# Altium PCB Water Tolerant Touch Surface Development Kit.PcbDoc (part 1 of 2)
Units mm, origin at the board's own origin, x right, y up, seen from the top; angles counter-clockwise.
Board outline 95 x 75 mm, 2 copper layers (Top Layer, Bottom Layer); 89 components, 87 nets, 311 pads, 203 vias.
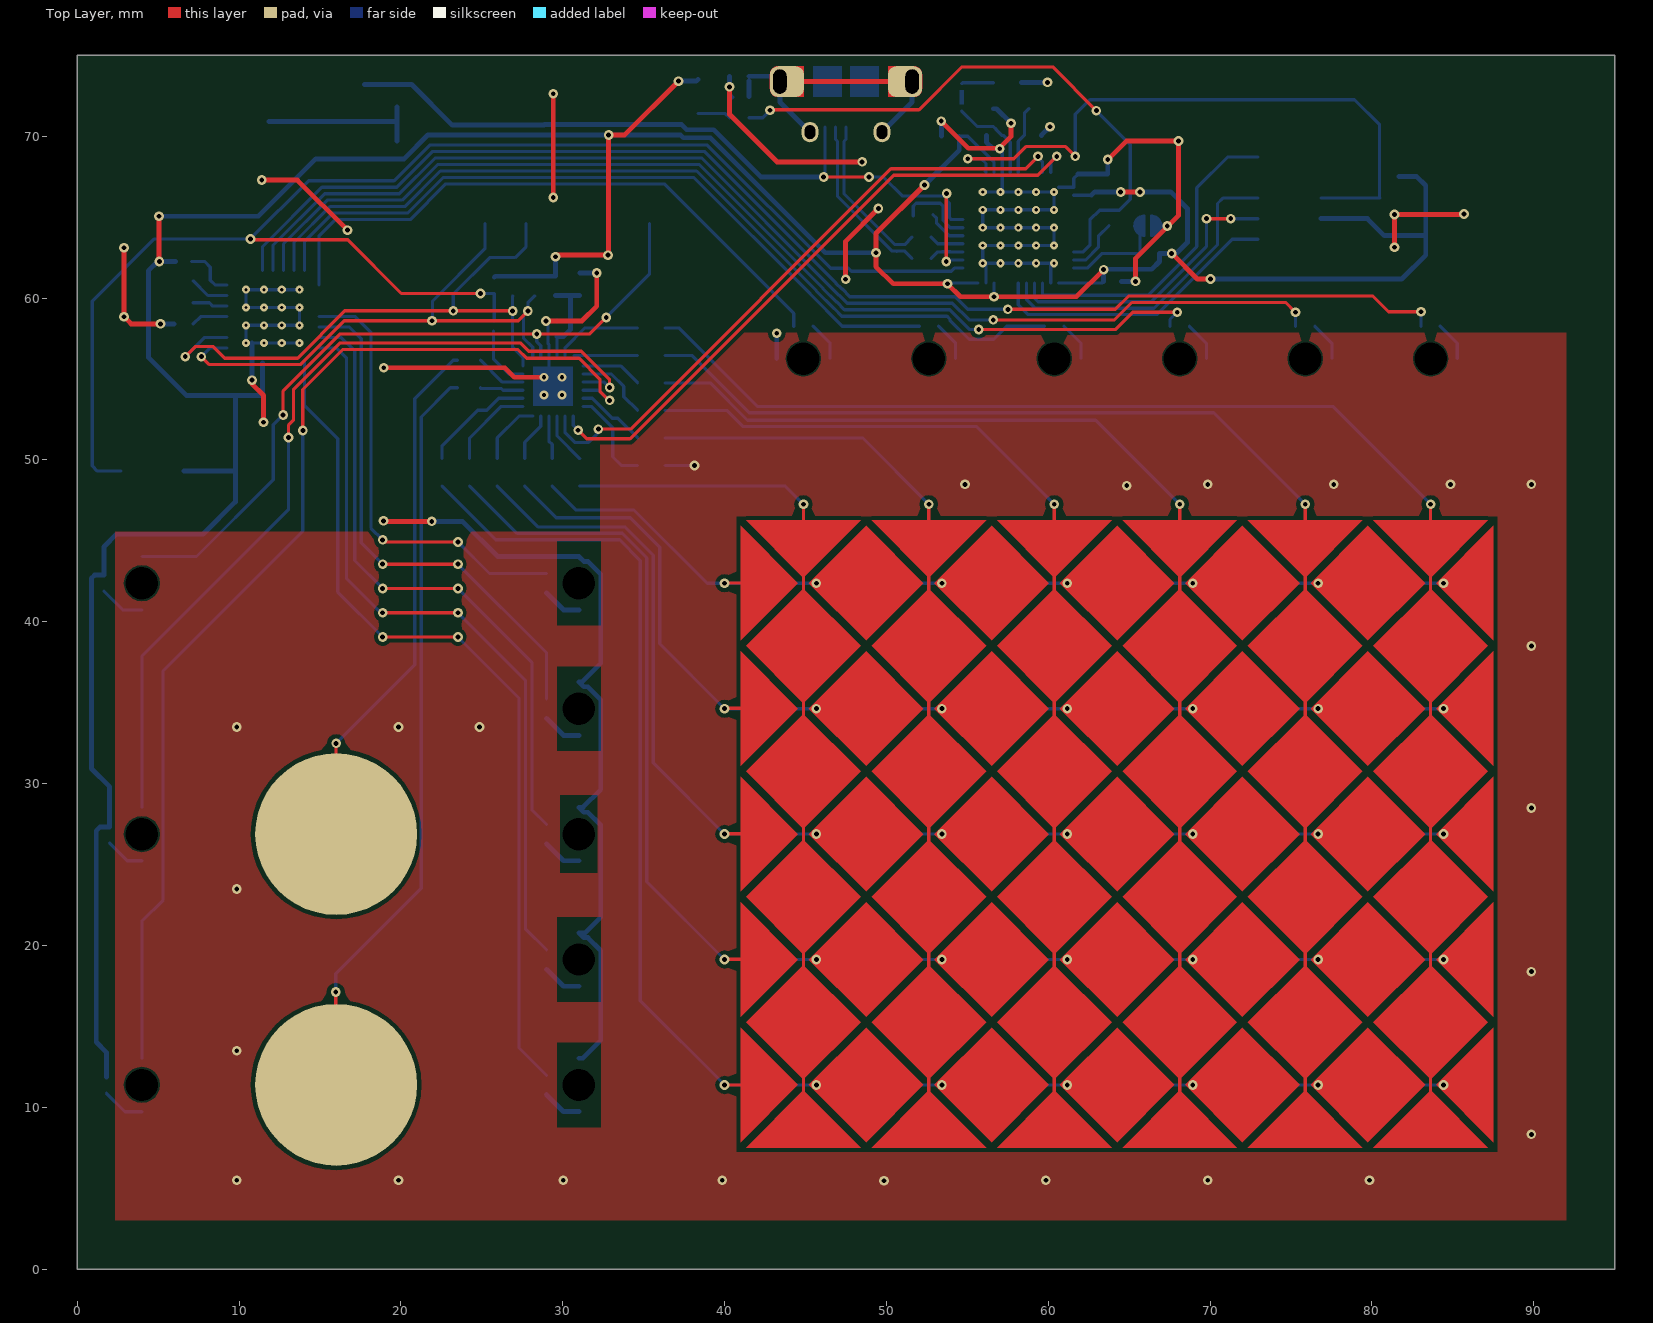
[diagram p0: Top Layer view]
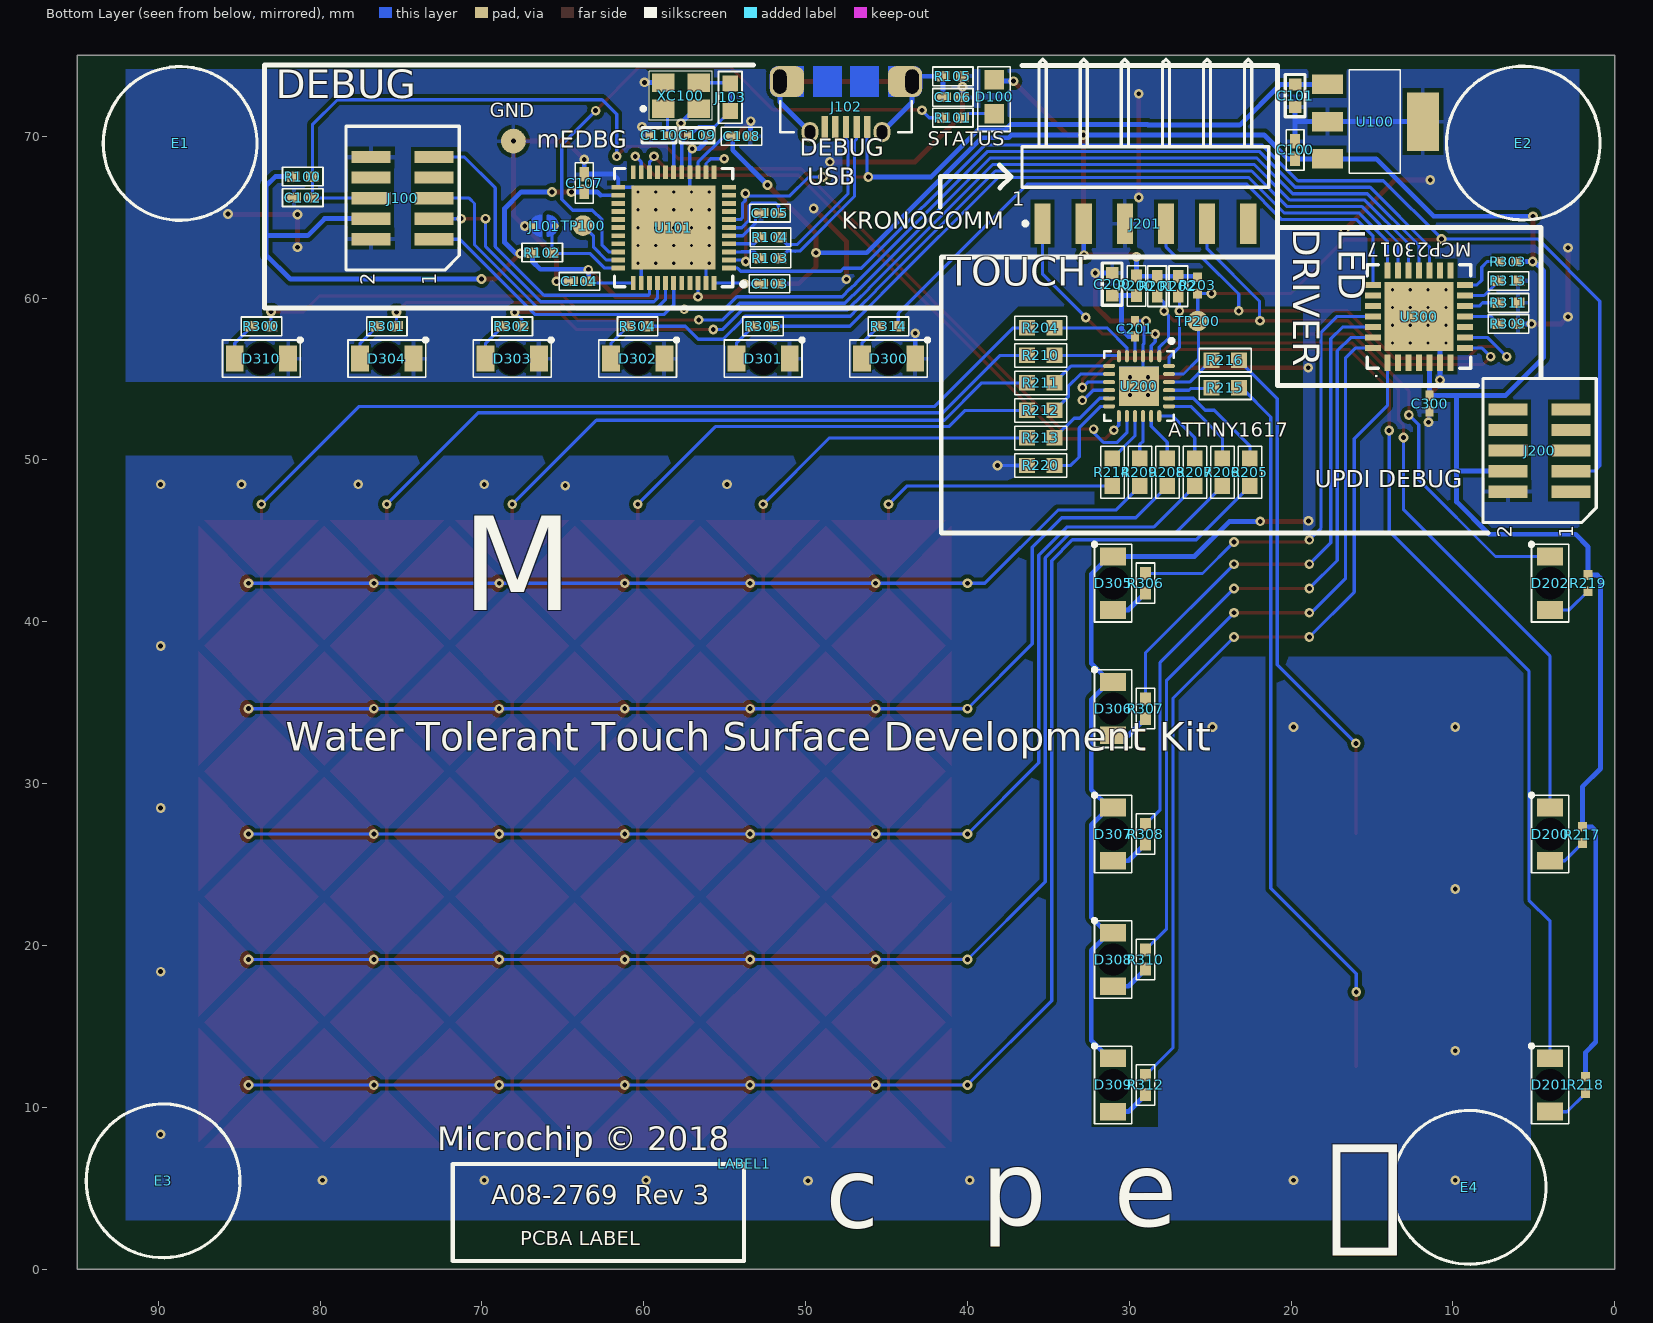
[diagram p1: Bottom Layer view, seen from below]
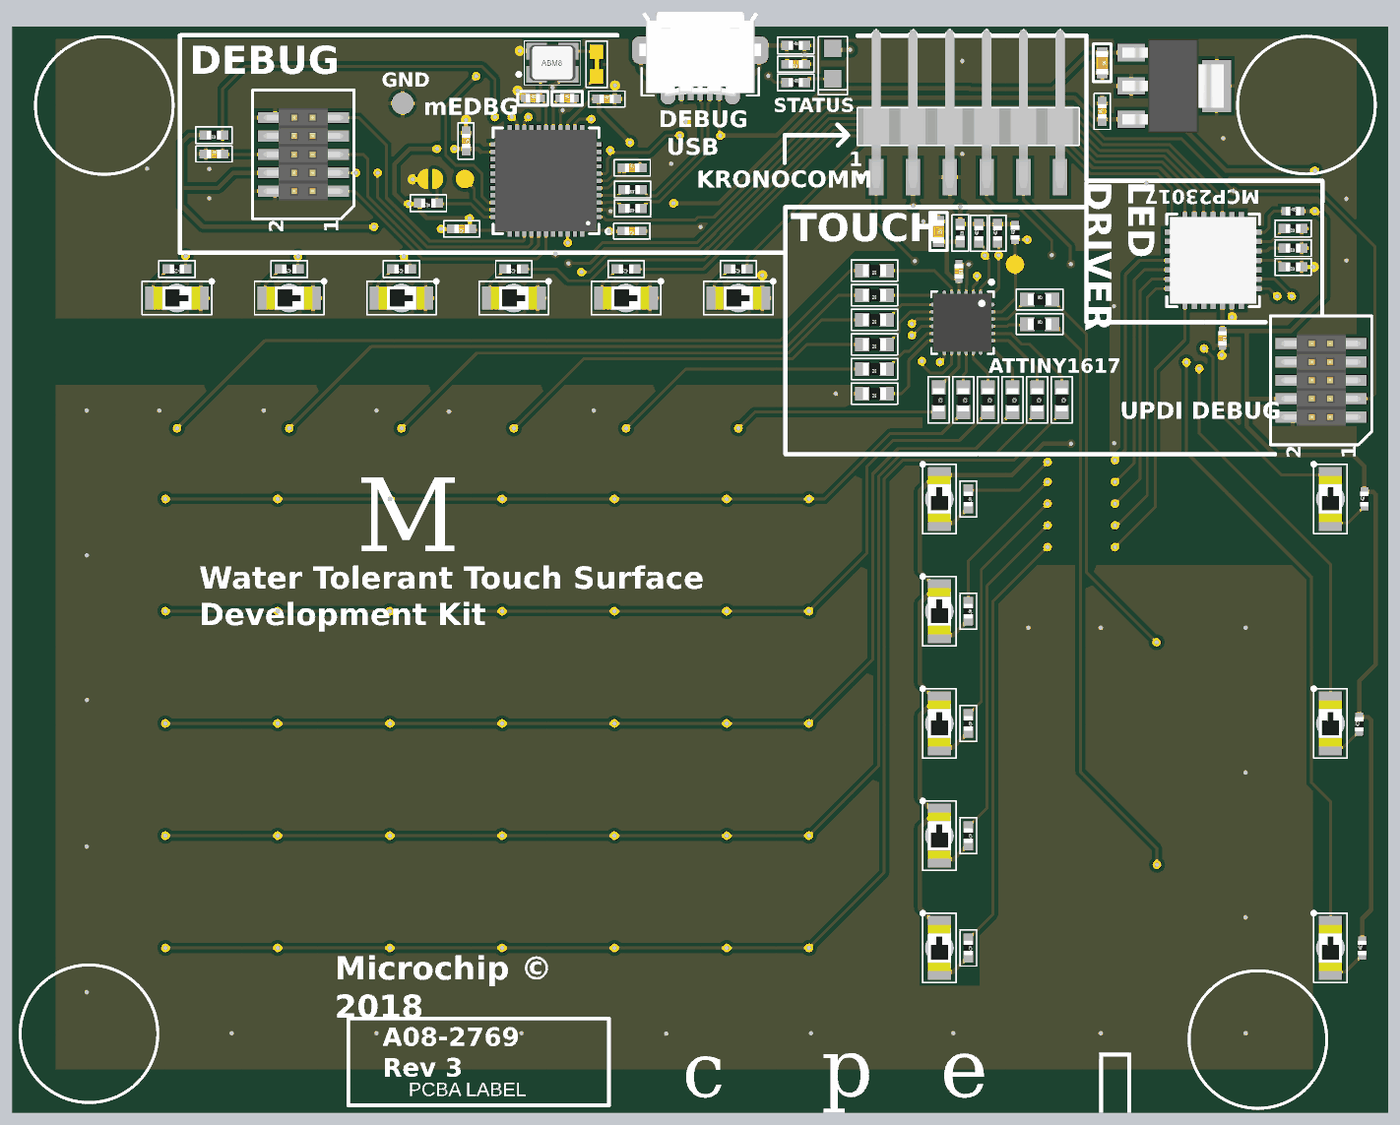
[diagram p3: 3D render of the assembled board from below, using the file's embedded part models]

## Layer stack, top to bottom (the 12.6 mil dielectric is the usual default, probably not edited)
Top Solder: solder mask 0.0102, Solder Resist, Dk 3.5
Top Layer: signal copper 0.0356
Dielectric 1: dielectric 0.32, FR-4, Dk 4.8
Bottom Layer: signal copper 0.0356
Bottom Solder: solder mask 0.0102, Solder Resist, Dk 3.5

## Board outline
0.007,0 0.007,75 95.007,75 95.007,0

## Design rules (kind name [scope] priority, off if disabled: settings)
AcuteAngle [All] p1: minimum=7.00000000000000E+0001 checktracksonly=FALSE
AssemblyTestPointUsage "Schematic Assembly Testpoint Usage_4" [InNet('NetJ103_1')] p1: valid=1
AssemblyTestPointUsage "Schematic Assembly Testpoint Usage_3" [InNet('XTAL1')] p2: valid=1
AssemblyTestPointUsage "Schematic Assembly Testpoint Usage_2" [InNet('XTAL2')] p3: valid=1
AssemblyTestPointUsage "Schematic Assembly Testpoint Usage_1" [InNet('D_P')] p4: valid=1
AssemblyTestPointUsage "Schematic Assembly Testpoint Usage" [InNet('D_N')] p5: valid=1
AssemblyTestPointUsage [All] p6: allowmultiple=TRUE
AssemblyTestpoint [(IsPad And OnMultiLayer)] p1: testpointundercomponent=TRUE minsize=0.55 maxsize=2 preferedsize=0.8 minholesize=0 maxholesize=1 preferedholesize=0.25 testpointgrid=0.025 usegrid=FALSE gridtolerance=0 allowsidebottom=TRUE minspacing=1.27 compbodyclearance=0.127
Clearance Clearance_AP4-00115 [All vs HasFootprint('AP4-00115')] p1: gap=0.1 ignorepadtopadclearanceinfootprint=FALSE except(0: Arc-Hole Track-Hole SMDPad-Hole THPad-Hole Via-Hole Fill-Hole Poly-Hole Region-Hole Text-Hole)
Clearance Clearance_KEEPOUT [IsKeepOut] p2: gap=0.4 ignorepadtopadclearanceinfootprint=FALSE except(0: Arc-Hole Track-Hole SMDPad-Hole THPad-Hole Via-Hole Fill-Hole Poly-Hole Region-Hole Text-Hole)
Clearance Clearance_POLY [InPolygon] p3: gap=0.25 ignorepadtopadclearanceinfootprint=FALSE except(0: Arc-Hole Track-Hole SMDPad-Hole THPad-Hole Via-Hole Fill-Hole Poly-Hole Region-Hole Text-Hole)
Clearance [All] p4: gap=0.2 ignorepadtopadclearanceinfootprint=FALSE except(0: Arc-Hole Track-Hole SMDPad-Hole THPad-Hole Via-Hole Fill-Hole Poly-Hole Region-Hole Text-Hole)
ComponentClearance [All] p1: gap=0.1 collisioncheckmode=3 verticalgap=0.1 showdistances=FALSE
DiffPairsRouting [All] p1: maxlimit=0.3 minlimit=0.2 mostfreqgap=0.2 toplayer_minwidth=0.18 toplayer_maxwidth=0.2 toplayer_prefwidth=0.2 bottomlayer_minwidth=0.18 bottomlayer_maxwidth=0.2 bottomlayer_prefwidth=0.2 maxuncoupledlength=20
FabricationTestPointUsage TestPointUsage [All] p1: valid=0 allowmultiple=TRUE
FabricationTestpoint Testpoint [(IsPad And OnMultiLayer)] p1: side=2 testpointundercomponent=TRUE minsize=0.55 maxsize=2 preferedsize=0.8 minholesize=0 maxholesize=1 preferedholesize=0.25 testpointgrid=0 allowsidebottom=TRUE usegrid=FALSE gridtolerance=0 minspacing=1.27 compbodyclearance=0.127
HoleSize [All] p1: absolutevalues=TRUE maxlimit=10 minlimit=0.2 maxpercent=80.000 minpercent=20.000
HoleToHoleClearance [All] p1: gap=0.45 allowstackedmicrovias=TRUE
MinimumAnnularRing [All] p1: minimumring=0.15
MinimumSolderMaskSliver MinimumSolderMaskSliver_1 [InPadClass('All Pads') And OnLayer('Bottom Layer') vs HasFootprint('AP6-00375')] p1: minsoldermaskwidth=0.075
MinimumSolderMaskSliver [All] p2: minsoldermaskwidth=0.1
PlaneClearance [All] p1: clearance=0.3
PlaneConnect PlaneConnect_1 [InComponent('U102')] p1: planeconnectstyle=Direct reliefexpansion=0.508 reliefentries=4 reliefconductorwidth=0.254 reliefairgap=0.254
PlaneConnect PlaneConnect_50mil [HasFootprint('AP8-00257')] p2: planeconnectstyle=Relief reliefexpansion=0.2 reliefentries=4 reliefconductorwidth=0.2 reliefairgap=0.2
PlaneConnect PlaneConnect_VIA [IsVia] p3: planeconnectstyle=Direct reliefexpansion=0.508 reliefentries=4 reliefconductorwidth=0.254 reliefairgap=0.254
PlaneConnect [All] p4: planeconnectstyle=Relief reliefexpansion=0.508 reliefentries=4 reliefconductorwidth=0.254 reliefairgap=0.254
PolygonConnect PolygonConnect_VIA [IsVia] p1: connectstyle=Direct reliefconductorwidth=0.254 reliefentries=4 polygonreliefangle="90 Angle" airgapwidth=0.254
PolygonConnect [All] p2: connectstyle=Relief reliefconductorwidth=0.254 reliefentries=4 polygonreliefangle="90 Angle" airgapwidth=0.254
RoutingVias [All] p1: holewidth=0.3 width=0.6 viastyle="Through Hole" minholewidth=0.3 minwidth=0.6 maxholewidth=0.5 maxwidth=1
SMDNeckDown [All] p1: percent=90.000
SilkToSilkClearance SilkToSilkClearance_Text [IsText vs IsText] p1: silktosilkclearance=0
SilkToSilkClearance [All] p2: silktosilkclearance=0.1
SilkToSolderMaskClearance SilkscreenOverComponentPads [IsPad] p1: minsilkscreentomaskgap=0.1 clearancetoexposedcopper=TRUE
SolderMaskExpansion SolderMaskTenting [IsVia AND NOT (IsFabTestpoint OR IsAssyTestpoint)] p1: expansion=-1
SolderMaskExpansion [All] p2: expansion=0.05
ViasUnderSMD [All] p1: allowed=FALSE
Width Width_Jumper [HasFootprint('AP9-00034')] p1: maxlimit=0.254 minlimit=0.1 preferedwidth=0.1
Width [All] p2: maxlimit=0.3 minlimit=0.2 preferedwidth=0.2
17 further rules are at their usual default settings.

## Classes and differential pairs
component class "Target MCU": C200 C201 D200 D201 D202 J200 J201 R200 R201 R202 R203 R204 R205 R206 R207 R208 R209 R210 R211 R212 R213 R214 R215 R216 R217 R218 R219 R220 TP200 U200
component class SENSORS: C300 D300 D301 D302 D303 D304 D305 D306 D307 D308 D309 D310 R300 R301 R302 R303 R304 R305 R306 R307 R308 R309 R310 R311 R312 R313 R314 U300
component class "Water Tolerant Touch Surface Development Kit_TopLevel": E1 E2 E3 E4 LABEL1 PCB1 PCBADOC1 TEST1 TESTDOC1
component class EDBG: C100 C101 C102 C103 C104 C105 C106 C107 C108 C109 C110 D100 J100 J101 J102 J103 R100 R101 R102 R103 R104 R105 TP100 U100 U101 XC100
differential pair USBD: +USBD_P -USBD_N
differential pair D: +D_P -D_N

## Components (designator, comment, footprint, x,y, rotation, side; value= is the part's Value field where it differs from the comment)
C100 "" AP1-00001 19.757,69.15 r90 bottom value=1u
C101 "CAP-NONPOL" AP1-00039 19.757,72.5 r270 bottom value=4.7uF
C102 "" AP1-00001 81.077,66.206 r180 bottom value=100n
C103 "" AP1-00001 52.225,60.88 r0 bottom value=100n
C104 "" AP1-00001 63.975,61.03 r0 bottom value=100n
C105 "" AP1-00001 52.207,65.25 r180 bottom value=1u
C106 "" AP1-00001 40.907,72.4 r0 bottom value=4.7n
C107 "" AP1-00001 63.677,67.106 r270 bottom value=100n
C108 "" AP1-00001 53.957,70 r180 bottom value=100n
C109 "" AP1-00038 56.707,70.05 r0 bottom value=12pF
C110 "" AP1-00038 59.057,70.05 r0 bottom value=12pF
C200 "CAP-NONPOL" AP1-00039 31.057,60.85 r270 bottom value=4.7uF
C201 "" AP1-00053 29.65,58.105 r270 bottom value=100n
C300 "" AP1-00053 11.45,53.48 r270 bottom value=100n
D100 "" AP4-00013 38.357,72.45 r90 bottom value=EL17-21SYGC
D200 "LED_21" AP4-00115 4,26.877 r90 bottom value=LTST-C250KRKT
D201 "LED_21" AP4-00115 4,11.376 r90 bottom value=LTST-C250KRKT
D202 "LED_21" AP4-00115 4,42.38 r90 bottom value=LTST-C250KRKT
D300 "LED_21" AP4-00115 44.876,56.256 r180 bottom value=LTST-C250KRKT
D301 "LED_21" AP4-00115 52.627,56.256 r180 bottom value=LTST-C250KRKT
D302 "LED_21" AP4-00115 60.378,56.256 r180 bottom value=LTST-C250KRKT
D303 "LED_21" AP4-00115 68.129,56.256 r180 bottom value=LTST-C250KRKT
D304 "LED_21" AP4-00115 75.88,56.256 r180 bottom value=LTST-C250KRKT
D305 "LED_21" AP4-00115 31,42.38 r90 bottom value=LTST-C250KRKT
D306 "LED_21" AP4-00115 31,34.629 r90 bottom value=LTST-C250KRKT
D307 "LED_21" AP4-00115 31,26.878 r90 bottom value=LTST-C250KRKT
D308 "LED_21" AP4-00115 31,19.127 r90 bottom value=LTST-C250KRKT
D309 "LED_21" AP4-00115 31,11.376 r90 bottom value=LTST-C250KRKT
D310 "LED_21" AP4-00115 83.631,56.256 r180 bottom value=LTST-C250KRKT
E1 "RUBBER FEET" AP8-01069 88.65,69.55 r180 bottom value=SJ61A4
E2 "RUBBER FEET" AP8-01069 5.657,69.575 r180 bottom value=SJ61A4
E3 "RUBBER FEET" AP8-01069 89.707,5.45 r180 bottom value=SJ61A4
E4 "RUBBER FEET" AP8-01069 9.007,5.05 r180 bottom value=SJ61A4
J100 "HEADER 2x5" AP8-00109 74.907,66.175 r90 bottom value=20021121-00010C4LF
J101 "" AP9-00034 66.15,64.45 r180 bottom value=SMD-STRAP_OPEN
J102 "2,000 pieces per reel" AP8-00852 47.507,73.375 r0 bottom locked value=ZX62D-AB-5P8
J103 "" AP9-00044 54.657,72.4 r270 bottom net-tie value=SMD-STRAP_0603_CLOSED
J200 "HEADER 2x5" AP8-00109 4.65,50.575 r90 bottom value=20021121-00010C4LF
J201 "BG301-06-X-XXXX-X-X_revC" BG301-06-X-XXXX-X-X_revC 29.007,64.6 r180 bottom
LABEL1 "PCBA_LABEL" AP8-00317 53.807,6.5 r0 bottom value="PCBA Label"
R100 "" AP2-00000 81.077,67.506 r0 bottom value=100k
R101 "R2" AP2-00000 40.907,71.145 r180 bottom value=330R
R102 "" AP2-00000 66.277,62.806 r0 bottom value=100k
R103 "" AP2-00000 52.182,62.45 r0 bottom value=22R
R104 "" AP2-00000 52.182,63.75 r0 bottom value=22R
R105 "" AP2-00000 40.907,73.7 r180 bottom value=1M
R200 "" AP2-00000 29.557,60.75 r270 bottom value=0R
R201 "R2" AP2-00000 28.275,60.73 r90 bottom value=4.7k
R202 "R2" AP2-00000 26.975,60.73 r90 bottom value=4.7k
R203 "" AP2-00011 25.775,60.78 r90 bottom value=1k
R204 "R2" AP2-00001 35.475,58.155 r0 bottom value=100k
R205 "R2" AP2-00001 22.55,49.23 r270 bottom value=100k
R206 "R2" AP2-00001 24.25,49.23 r270 bottom value=100k
R207 "R2" AP2-00001 25.95,49.23 r270 bottom value=100k
R208 "R2" AP2-00001 27.65,49.23 r270 bottom value=100k
R209 "R2" AP2-00001 29.35,49.23 r270 bottom value=100k
R210 "R2" AP2-00001 35.475,56.455 r0 bottom value=100k
R211 "R2" AP2-00001 35.475,54.755 r0 bottom value=100k
R212 "R2" AP2-00001 35.475,53.055 r0 bottom value=100k
R213 "R2" AP2-00001 35.475,51.355 r0 bottom value=100k
R214 "R2" AP2-00001 31.05,49.23 r270 bottom value=100k
R215 "R2" AP2-00001 24.075,54.455 r180 bottom value=10k
R216 "R2" AP2-00001 24.075,56.155 r180 bottom value=10k
R217 "" AP2-00011 2.007,26.822 r90 bottom value=1k
R218 "" AP2-00011 1.807,11.376 r90 bottom value=1k
R219 "" AP2-00011 1.657,42.38 r90 bottom value=1k
R220 "R2" AP2-00001 35.475,49.655 r0 bottom value=10k
R300 "R2" AP2-00000 83.631,58.256 r0 bottom value=330R
R301 "R2" AP2-00000 75.88,58.256 r0 bottom value=330R
R302 "R2" AP2-00000 68.129,58.256 r0 bottom value=330R
R303 "" AP2-00011 6.577,62.256 r180 bottom value=1k
R304 "R2" AP2-00000 60.378,58.256 r0 bottom value=330R
R305 "R2" AP2-00000 52.627,58.256 r0 bottom value=330R
R306 "R2" AP2-00000 29,42.38 r270 bottom value=330R
R307 "R2" AP2-00000 29,34.629 r270 bottom value=330R
R308 "R2" AP2-00000 29,26.878 r270 bottom value=330R
R309 "R2" AP2-00000 6.577,58.406 r0 bottom value=0R
R310 "R2" AP2-00000 29,19.127 r270 bottom value=330R
R311 "R2" AP2-00000 6.577,59.706 r0 bottom value=0R
R312 "R2" AP2-00000 29,11.376 r270 bottom value=330R
R313 "R2" AP2-00000 6.577,61.056 r0 bottom value=0R
R314 "R2" AP2-00000 44.876,58.256 r0 bottom value=330R
TP100 "" AP8-00010 63.757,64.475 r90 bottom value=TESTPAD
TP200 "" AP8-00010 25.775,58.58 r90 bottom value=TESTPAD
U100 "MCP1825S-3302E_DB" AP6-00231 17.757,73.2 r270 bottom value=MCP1825S-3302E/DB
U101 "" AP6-00375 58.157,64.35 r0 bottom value=ATmega32U4-MUR
U200 "ATtiny807" AP6-00459 29.4,54.555 r270 bottom value=ATtiny1617-MNRES
U300 "MCP23017-E_ML" AP6-00497 12.1,58.855 r90 bottom value=MCP23017
XC100 "" AP7-00061 57.707,72.5 r180 bottom value=16.0MHz

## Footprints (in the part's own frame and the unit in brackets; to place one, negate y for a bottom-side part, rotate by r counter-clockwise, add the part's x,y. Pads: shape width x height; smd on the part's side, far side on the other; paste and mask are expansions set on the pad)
AP1-00001 [mm] "Standard 0402 SMD capacitor footprint"
  rect 0.9x0.6 smd: 1(-0.55,0) 2(0.55,0)
  silkscreen extent -1.25,-0.55 1.25,0.55, body extent -0.5,-0.3 0.5,0.3, height 0.2
AP1-00038 [mm] "Generic pad 0402, spacing 0.45mm"
  rect 0.6x0.5 smd: 1(-0.525,0) 2(0.525,0)
  silkscreen extent -1.05,-0.48 1.05,0.47, body extent -0.5,-0.3 0.5,0.3, height 0.2
AP1-00039 [mil] "Capacitor 0603 Hight 0.8mm"
  rect 30x30 smd: 1(-27.5,0) 2(27.5,0)
  silkscreen extent -52,-24 51,24, body extent -31,-16 32,16, height 12
AP1-00053 [mm] "Chip Capacitor, 2-Leads, Body 1.0x0.5mm, IPC High Density"
  rect 0.65x0.5 smd: 1(-0.475,0) 2(0.475,0)
  body extent -0.5,-0.3 0.5,0.3, height 0.2
AP2-00000 [mm] "Standard 0402 SMD resistor footprint"
  rect 0.8x0.65 smd: 1(-0.6,0) 2(0.6,0)
  silkscreen extent -1.25,-0.58 1.25,0.58, body extent -0.5,-0.3 0.5,0.3, height 0.2
AP2-00001 [mm]
  rect 1x0.95 smd: 1(-0.85,0) 2(0.85,0)
  silkscreen extent -1.6,-0.72 1.6,0.72, body extent -0.8,-0.4 0.8,0.4, height 0.3
AP2-00011 [mm] "Chip Resistor, 2-Leads, Body 1,0x0,5mm, IPC High Density"
  rect 0.6x0.55 smd: 1(-0.5,0) 2(0.5,0)
  body extent -0.5,-0.3 0.5,0.3, height 0.2
AP4-00013 [mm] "0805 diode footprint"
  rect 1.2x1.2 smd: 1(-1.05,0) 2(1.05,0)
  silkscreen extent -2.16,-1 1.85,1, body extent -1,-0.63 1,0.63, height 1.1
AP4-00115 [mm] "3.2x1.6mm, 1305, Reverse mount SMD LED"
  round 0 hole 2 unplated: 0(0,0)
  rect 1.1x1.6 smd: 1(-1.65,0) 2(1.65,0)
  silkscreen extent -2.4,-1.15 2.5,1.25, body extent -1.6,-0.8 1.6,0.8, height 0.29
AP6-00231 [mm]
  rect 1.2x1.9 smd: 1(0,0) 2(2.3,0) 3(4.6,0)
  rect 3.6x2 smd: 4(2.3,5.9)
  silkscreen extent -0.9,1.35 5.5,4.5, body extent -0.95,-0.6 5.55,6.4, height 1.64
AP6-00375 [mm] "QFN, 44-Leads, Body 7,00x7,00mm, Pitch 0,50mm, Thermal Pad 5,20x5,20mm, IPC Medium Density"
  rect 0.85x0.3 smd mask+0.06: 1(-3.425,2.5) 2(-3.425,2) 3(-3.425,1.5) 4(-3.425,1) 5(-3.425,0.5) 6(-3.425,0) 7(-3.425,-0.5) 8(-3.425,-1) 9(-3.425,-1.5) 10(-3.425,-2) 11(-3.425,-2.5) 23(3.425,-2.5) 24(3.425,-2) 25(3.425,-1.5) 26(3.425,-1) 27(3.425,-0.5) 28(3.425,0) 29(3.425,0.5) 30(3.425,1) 31(3.425,1.5) 32(3.425,2) 33(3.425,2.5)
  rect 0.3x0.85 smd mask+0.06: 12(-2.5,-3.425) 13(-2,-3.425) 14(-1.5,-3.425) 15(-1,-3.425) 16(-0.5,-3.425) 17(0,-3.425) 18(0.5,-3.425) 19(1,-3.425) 20(1.5,-3.425) 21(2,-3.425) 22(2.5,-3.425) 34(2.5,3.425) 35(2,3.425) 36(1.5,3.425) 37(1,3.425) 38(0.5,3.425) 39(0,3.425) 40(-0.5,3.425) 41(-1,3.425) 42(-1.5,3.425) 43(-2,3.425) 44(-2.5,3.425)
  rect 5.2x5.2 smd: 45(0,0)
  silkscreen extent -4.42,-3.65 3.65,3.65, body extent -3.5,-3.5 3.5,3.5, height 0.89
AP6-00459 [mm] "QFN, 24-Leads, Body 4,00x4,00mm, Pitch 0,50mm, Thermal Pad 2,45x2,45mm, IPC High Density"
  oval 0.75x0.25 smd: 1(-1.85,1.25) 2(-1.85,0.75) 3(-1.85,0.25) 4(-1.85,-0.25) 5(-1.85,-0.75) 6(-1.85,-1.25) 13(1.85,-1.25) 14(1.85,-0.75) 15(1.85,-0.25) 16(1.85,0.25) 17(1.85,0.75) 18(1.85,1.25)
  oval 0.25x0.75 smd: 7(-1.25,-1.85) 8(-0.75,-1.85) 9(-0.25,-1.85) 10(0.25,-1.85) 11(0.75,-1.85) 12(1.25,-1.85) 19(1.25,1.85) 20(0.75,1.85) 21(0.25,1.85) 22(-0.25,1.85) 23(-0.75,1.85) 24(-1.25,1.85)
  rect 2.45x2.45 smd: 25(0,0)
  silkscreen extent -2.92,-2.15 2.15,2.15, body extent -2,-2 2,2, height 0.9
AP6-00497 [mm] "QFN, 28-Leads, Body 6x6mm (max), Pitch 0.65mm, IPC Medium Density"
  rect 1x0.37 smd: 1(-2.85,1.95) 2(-2.85,1.3) 3(-2.85,0.65) 4(-2.85,0) 5(-2.85,-0.65) 6(-2.85,-1.3) 7(-2.85,-1.95) 15(2.85,-1.95) 16(2.85,-1.3) 17(2.85,-0.65) 18(2.85,0) 19(2.85,0.65) 20(2.85,1.3) 21(2.85,1.95)
  rect 0.37x1 smd: 8(-1.95,-2.85) 9(-1.3,-2.85) 10(-0.65,-2.85) 11(0,-2.85) 12(0.65,-2.85) 13(1.3,-2.85) 14(1.95,-2.85) 22(1.95,2.85) 23(1.3,2.85) 24(0.65,2.85) 25(0,2.85) 26(-0.65,2.85) 27(-1.3,2.85) 28(-1.95,2.85)
  rect 4.25x4.25 smd: 29(0,0)
  silkscreen extent -3.2,-3.2 3.2,3.2, body extent -3,-3 3,3, height 1.02
AP7-00061 [mm] "TSX-3225"
  rect 1.4x1.15 smd: 1(-1.1,-0.8) 2(1.1,-0.8) 3(1.1,0.8) 4(-1.1,0.8)
  silkscreen extent -2.43,-1.53 1.95,1.53, body extent -1.6,-1.24 1.6,1.24, height 0.8
AP8-00010 [mm] "Testpad 50mil"
  round 1.27 smd paste-0.635: 1(0,0)
AP8-00109 [mm]
  rect 0.76x2.4 smd: 1(-2.54,-1.95) 2(-2.54,1.95) 3(-1.27,-1.95) 4(-1.27,1.95) 5(0,-1.95) 6(0,1.95) 7(1.27,-1.95) 8(1.27,1.95) 9(2.54,-1.95) 10(2.54,1.95)
  silkscreen extent -4.44,-3.5 4.44,3.5, body extent -3.18,-2.75 3.17,2.75, height 4.7
AP8-00317 [mm] "Placement area for 18x6mm sticker"
  silkscreen extent 0,0 18,6
AP8-00852 [mm] "Hirose, ZX Series, USB Micro-AB Recept-RA"
  rect 0.4x1.35 smd: 1(-1.3,2.8) 2(-0.65,2.8) 3(0,2.8) 4(0.65,2.8) 5(1.3,2.8)
  rrect52% 2.1x1.9 hole 0.825 slot 1.5 at 90 deg copper offset 0.437,0: 6(-4.088,0)
  rrect52% 2.1x1.9 on Bottom Paste: 6(-3.6,0) 7(3.6,0)
  rrect52% 2.1x1.9 hole 0.825 slot 1.5 at 90 deg copper offset -0.437,0: 7(4.088,0)
  rrect100% 1.05x1.25 hole 0.65 slot 0.85 at 90 deg: 8(-2.225,3.125) 9(2.225,3.125)
  rrect100% 1.05x1.25 on Bottom Paste: 8(-2.225,3.125) 9(2.225,3.125)
  Top Layer region: 0.249,0.95 2.049,0.95 2.049,-0.95 0.249,-0.95
  Top Layer region: -2.049,0.95 -0.249,0.95 -0.249,-0.95 -2.049,-0.95
  Top Layer region: 2.6,-0.95 4.2,-0.95 4.294,-0.941 4.381,-0.915 4.434,-0.891 4.48,-0.862 4.52,-0.832 4.565,-0.791 4.596,-0.753 4.622,-0.716 4.647,-0.673 4.66,-0.64 4.676,-0.6 4.688,-0.55 4.696,-0.505 4.7,-0.45 4.7,0.45 4.696,0.503 4.689,0.548 4.677,0.599 4.661,0.641 4.641,0.683 4.617,0.724 4.589,0.761 4.56,0.797 4.521,0.831 4.483,0.86 4.439,0.888 4.397,0.908 4.354,0.924 4.301,0.939 4.248,0.946 4.2,0.95 2.6,0.95
  Top Layer region: -2.6,0.95 -4.2,0.95 -4.294,0.941 -4.381,0.915 -4.434,0.891 -4.48,0.862 -4.52,0.832 -4.565,0.791 -4.596,0.753 -4.622,0.716 -4.647,0.673 -4.66,0.64 -4.676,0.6 -4.688,0.55 -4.696,0.505 -4.7,0.45 -4.7,-0.45 -4.696,-0.503 -4.689,-0.548 -4.677,-0.599 -4.661,-0.641 -4.641,-0.683 -4.617,-0.724 -4.589,-0.761 -4.56,-0.797 -4.521,-0.831 -4.483,-0.86 -4.439,-0.888 -4.397,-0.908 -4.354,-0.924 -4.301,-0.939 -4.248,-0.946 -4.2,-0.95 -2.6,-0.95
  Top Layer pour cut-out: -3.75,1.975 3.75,1.975 3.75,-1.325 -3.75,-1.325
  Bottom Layer region: -2.6,0.95 -4.2,0.95 -4.294,0.941 -4.381,0.915 -4.434,0.891 -4.48,0.862 -4.52,0.832 -4.565,0.791 -4.596,0.753 -4.622,0.716 -4.647,0.673 -4.66,0.64 -4.676,0.6 -4.688,0.55 -4.696,0.505 -4.7,0.45 -4.7,-0.45 -4.696,-0.503 -4.689,-0.548 -4.677,-0.599 -4.661,-0.641 -4.641,-0.683 -4.617,-0.724 -4.589,-0.761 -4.56,-0.797 -4.521,-0.831 -4.483,-0.86 -4.439,-0.888 -4.397,-0.908 -4.354,-0.924 -4.301,-0.939 -4.248,-0.946 -4.2,-0.95 -2.6,-0.95
  Bottom Layer region: 2.6,-0.95 4.2,-0.95 4.294,-0.941 4.381,-0.915 4.434,-0.891 4.48,-0.862 4.52,-0.832 4.565,-0.791 4.596,-0.753 4.622,-0.716 4.647,-0.673 4.66,-0.64 4.676,-0.6 4.688,-0.55 4.696,-0.505 4.7,-0.45 4.7,0.45 4.696,0.503 4.689,0.548 4.677,0.599 4.661,0.641 4.641,0.683 4.617,0.724 4.589,0.761 4.56,0.797 4.521,0.831 4.483,0.86 4.439,0.888 4.397,0.908 4.354,0.924 4.301,0.939 4.248,0.946 4.2,0.95 2.6,0.95
  silkscreen extent -4.05,1.22 4.05,3.13, body extent -4.32,-2.65 4.33,3.25, height 2.78
AP8-01069 [mm] "Rubber feet. 9.5mm Diam, 7.9mm high"
  silkscreen extent -4.75,-4.75 4.75,4.75
AP9-00034 [mm] "PCB implemented strap, open"
  round 0.4 smd paste-0.4 mask-0.4: 1(-0.675,0) 2(0.675,0)
  Top Layer region: 0.2,0.675 0.482,0.611 0.708,0.43 0.834,0.17 0.834,-0.12 0.708,-0.38 0.482,-0.561 0.2,-0.625 0.2,-0.625
  Top Layer region: -0.2,-0.625 -0.482,-0.561 -0.708,-0.38 -0.834,-0.12 -0.834,0.17 -0.708,0.43 -0.482,0.611 -0.2,0.675 -0.2,0.675
  Top Layer lines w0.1: -0.85,0 cw(c-0.2,0.025) -0.85,0 ; -0.85,0 cw(c-0.2,0.025) -0.2,0.675 -0.2,-0.625 cw(c-0.2,0.025) -0.85,0 ; 0.85,0.025 ccw(c0.2,0.025) 0.2,0.675 0.2,-0.625 ccw(c0.2,0.025) 0.473,-0.565 ccw(c0.2,0.025) 0.6,-0.487 ccw(c0.2,0.025) 0.85,0 ccw(c0.2,0.025) 0.85,0.025
AP9-00044 [mm]
  rect 1x0.95 smd paste-1: 1(-0.85,0) 2(0.85,0)
  Top Layer region: -0.45,0.15 0.45,0.15 0.45,-0.15 -0.45,-0.15
  silkscreen extent -1.6,-0.72 1.6,0.72, body extent -0.8,-0.4 0.8,0.4, height 0.3
BG301-06-X-XXXX-X-X_revC [mm] "2.54mm Pitch Pin Header,Single Row, Surface Mount, Horizontal, Natural LCP"
  rect 1x2.5 smd: 1(-6.35,0) 2(-3.81,0) 3(-1.27,0) 4(1.27,0) 5(3.81,0) 6(6.35,0)
  silkscreen extent -7.62,-0.12 7.62,10.15, body extent -7.62,-0.74 7.62,10.16, height 2.34

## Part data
C100 C105: library part A01-0286, "Ceramic capacitor, SMD 0402, X5R, 6.3V, +/-10% (de26942)", Manufacturer=Kemet, MPN=C0402C105K9PAC, TemperatureRange="-55 to 85 deg C", Tolerance=+/-10%
C101 C200: library part A01-0377, "Ceramic capacitor, SMD 0603, X5R, 10V, 10% (de31036)", Manufacturer="WALSIN Technology Corporation", MPN=0603X475K100CT, TemperatureRange="-55 - +85 deg C", Tolerance=10%
C102 C103 C104 C107 C108 C201 C300: library part A01-0246, "Ceramic capacitor, SMD 0402, X7R, 16V, +/-10%", Manufacturer=Kemet, MPN=C0402C104K4RACTU, TemperatureRange="-55 - +125 deg C", Tolerance="16V, +/-10%"
C106: library part A01-0046, "Ceramic capacitor, SMD 0402, X7R, 25V, +/-10% (de35287)", TemperatureRange="-55 - +125 deg C", Tolerance="25V, +/-10%"
C109 C110: library part A01-0355, "Ceramic capacitor, SMD 0402, NP0, 50V, +/-5% (de19819)", Manufacturer=Kyocera-elco, MPN=CM05CG120J50AH, TemperatureRange="-55 - +125 deg C", Tolerance=5%
D100: library part A10-0018, "LED, Green, Wave length=575nm, SMD 0805, ±70°", Manufacturer=Everlight, MPN=EL17-21SYGC, TemperatureRange="-40 - +85 deg C"
D200 D201 D202 D300 D301 D302 D303 D304 D305 D306 D307 D308 D309 D310: library part A10-0204, "LED, SMD, RED, 3.2x1.2mm, reverse mount"
E1 E2 E3 E4: library part A08-2771, "7.9mm adhesive feet diam 9.5mm"
J100 J200: library part A08-0022, "2x5 pin header, 1.27mm pitch, SMD", Manufacturer=HARWIN, MPN=M50-3600542
J101: library part A09-0483, "Default open SMD strap"
J102: library part A08-2112, "Micro USB AB Connector, Standard SMT + DIP", Manufacturer=HIROSE, MPN=ZX62D-AB-5P8(30)
J103: library part A09-0783, "Default closed SMD strap, 0603 size"
J201: "2.54mm Pitch Pin Header,Single Row, Surface Mount, Horizontal, Natural LCP"
LABEL1: library part A09-0611, "PCBA identification label PP Top White Gloss", Manufacturer="ACT Logimark AS", MPN=505462
R100 R102: library part A02-0260, "Thick film resistor, SMD 0402, 1/16W, 1%", Manufacturer=ASJ, MPN=CR10-1003-FK, TemperatureRange="-55� to +125�C", Tolerance="1 %"
R101: library part A02-0200, "Thick film resistor, SMD 0402, 1/16W, 1%", TemperatureRange="-55 - +125 deg C", Tolerance="1 %"
R103 R104: library part A02-0172, "Thick film resistor, SMD 0402, 1/16W, 1% (de23607)", Manufacturer=Samsung, MPN=RC100SF22R0CS, TemperatureRange="-55 - +125 deg C", Tolerance="1 %"
R105: library part A02-0284, "Thick film resistor, SMD 0402, 1/16W, 1%", Manufacturer=ASJ, MPN=CR10-1004-FK, TemperatureRange="-55 - +125 deg C", Tolerance="1 %"
R200 R309 R311 R313: library part A02-0163, "RES 0.0 OHM 1/16W 0402 SMD", Manufacturer=(n/a), MPN=RMCF0402ZT0R00, TemperatureRange="-55 - +125 deg C", Tolerance="1 %"
R201 R202: library part A02-0228, "Thick film resistor, SMD 0402, 1/16W, 1%", Manufacturer=PHYCOMP, MPN="2322 706 74702L", TemperatureRange="-55� to +125�C", Tolerance="1 %"
R203 R217 R218 R219 R303: library part A02-0212, "Thick film resistor, SMD 0402, 1/16W, 1%", TemperatureRange="-55 - +125 deg C", Tolerance="1 %"
R204 R205 R206 R207 R208 R209 R210 R211 R212 R213 R214: library part A02-0122, "Thick film resistor, SMD 0603, 1/10W, 1%", Manufacturer=Panasonic, MPN=ERJ-3EKF1003V, Tolerance="1 %"
R215 R216 R220: library part A02-0098, "Thick film resistor, SMD 0603, 1/10W, 1%", Manufacturer=KOA, MPN=RK73H1JTTD1002F, Tolerance="1 %"
R300 R301 R302 R304 R305 R306 R307 R308 R310 R312 R314: library part A02-0200, "Thick film resistor, SMD 0402, 1/16W, 1%", Manufacturer=ASJ, MPN=CR10-3300-FK, TemperatureRange="-55 - +125 deg C", Tolerance="1 %"
TP100 TP200: library part A08-0004, "Single SMD testpad"
U100: library part A06-1533, "LDO regulator, 3.3V fixed, 500mA, SOT-223"
U101: library part A06-0305, "ATmega32U4 QFN package", Manufacturer=ATMEL, MPN=ATmega32U4-MUR
U200: library part A06-1500, "Atmel 8-bit RISC MCU, QFN", Manufacturer=ATMEL, MPN=ATtiny1617-MNRES, TemperatureRange="-40°C +125°C"
U300: library part A06-1534, "16-Bit I/O Expander with I2C interface, 28-Lead QFN", Manufacturer="Microchip Technology Inc", MPN=MCP23017-E/ML, TemperatureRange="-40°C to +125°C"
XC100: library part A07-0078, "16MHz uXtal, 3.2 x 2.5 mm SMD, CL=9pF, 15PPM, ESR=80ohm(Max.", Manufacturer="Epson Toyocom", MPN="TSX-3225 16.0000MF09Z-AC3", TemperatureRange="-40°C to +85°C", Tolerance=15ppm

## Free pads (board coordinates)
  round 1.524 smd far side: 0(68.057,69.7)
  round 10 smd paste-12 mask-12: ""(16,11.38) ""(16,26.877)

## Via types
v1: diameter 0.6, hole 0.3, Top Layer to Bottom Layer, 103 vias
v2: diameter 0.6, hole 0.3, Top Layer to Bottom Layer, tented both sides, 55 vias
v3: diameter 0.5, hole 0.2, Top Layer to Bottom Layer, 41 vias
v4: diameter 0.55, hole 0.25, Top Layer to Bottom Layer, 4 vias

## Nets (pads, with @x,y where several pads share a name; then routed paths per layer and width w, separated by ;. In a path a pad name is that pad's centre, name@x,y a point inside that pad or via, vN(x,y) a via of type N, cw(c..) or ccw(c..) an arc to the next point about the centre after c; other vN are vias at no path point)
BUTTON2: pad.@16,11.38 R215.2 | length 45.3
  Top Layer w0.2: v1(15.977,17.12) 15.977,12.523 pad.@16,12.5
  Bottom Layer w0.2: v1(15.977,17.12) 15.977,18.256 21.257,23.536 21.257,52.65 23.062,54.455 R215.2@23.225,54.455 R215.2@23.5,54.455
BUTTON3: pad.@16,26.877 R216.2 | length 32.5
  Top Layer w0.2: pad.@16,26.877 v1(16,32.482)
  Bottom Layer w0.2: v1(16,32.482) 20.857,37.339 20.857,53.787 R216.2@23.225,56.155 R216.2@23.5,56.155
CLK_OUT: TP100.1 U101.32 | length 3.5
  Bottom Layer w0.2: U101.32@61.582,62.35 62.321,62.35 63.107,63.136 63.107,63.825 TP100.1@63.757,64.475
COL_1: R314.1 U300.22 | length 37.8
  Bottom Layer w0.2: U300.22@14.95,60.805 14.95,63.849 15.951,64.85 20.575,64.85 22.775,67.05 36.274,67.05 44.276,59.048 R314.1@44.276,58.256
COL_2: R305.1 U300.21 | length 45.2
  Bottom Layer w0.2: U300.21@14.05,61.705 14.05,63.515 15.785,65.25 20.41,65.25 22.61,67.45 38.111,67.45 45.285,60.275 45.285,60.249 47.279,58.256 R305.1@52.027,58.256
COL_3: R304.1 U300.20 | length 54.6
  Bottom Layer w0.2: U300.20@13.4,61.705 13.4,63.43 15.62,65.65 20.244,65.65 22.444,67.85 38.276,67.85 45.685,60.441 45.685,60.415 46.74,59.361 46.766,59.361 47.246,58.881 53.751,58.881 53.927,58.705 53.927,58.631 55.108,57.45 56.631,57.45 57.437,58.256 R304.1@59.778,58.256
COL_4: R302.1 U300.19 | length 64.8
  Top Layer w0.2: v1(55.707,58.05) 64.149,58.05 65.225,59.126 v1(67.975,59.126) v1@67.975,58.976
  Bottom Layer w0.2: U300.19@12.75,61.705 12.75,63.346 15.454,66.05 20.078,66.05 22.278,68.25 38.442,68.25 46.085,60.607 46.085,60.581 46.905,59.761 46.931,59.761 47.411,59.281 53.917,59.281 55.148,58.05 v1(55.707,58.05) ; R302.1@67.529,58.256 67.529,58.679 v1(67.975,59.126)
COL_5: R301.1 U300.18 | length 72.7
  Top Layer w0.2: v2(56.607,58.65) 64.099,58.65 65.175,59.726 74.675,59.726 v1(75.28,59.121)
  Bottom Layer w0.2: U300.18@12.1,61.705 12.1,63.262 15.288,66.45 19.913,66.45 22.113,68.65 38.608,68.65 46.485,60.772 46.485,60.746 47.071,60.161 47.097,60.161 47.577,59.681 54.083,59.681 55.113,58.65 v2(56.607,58.65) ; R301.1@75.28,58.256 v1(75.28,59.121)
COL_6: R300.1 U300.17 | length 81.2
  Top Layer w0.2: v2(57.507,59.3) 64.149,59.3 64.975,60.126 80.057,60.126 81.027,59.156 v1(83.031,59.156)
  Bottom Layer w0.2: U300.17@11.45,61.705 11.45,63.177 15.123,66.85 19.747,66.85 21.947,69.05 38.773,69.05 46.885,60.938 46.885,60.912 47.237,60.561 47.263,60.561 47.743,60.081 54.248,60.081 55.029,59.3 v2(57.507,59.3) ; R300.1@83.031,58.256 v1(83.031,59.156)
D_N: R103.2 U101.3 | length 2.1
  Bottom Layer w0.2: R103.2@52.782,62.45 53.182,62.85 53.446,62.85 53.451,62.855 53.948,62.855 53.954,62.85 U101.3@54.732,62.85
D_P: R104.2 U101.4 | length 2.1
  Bottom Layer w0.2: R104.2@52.782,63.75 53.182,63.35 U101.4@54.732,63.35
DRIVEN_SHIELD: R220.2 | length 1.8
  Bottom Layer w0.2: R220.2@36.325,49.655 v2(38.152,49.655)
  other v2: 49.857,5.46 9.857,5.489 19.857,5.489 30.031,5.489 39.857,5.489 59.857,5.489 69.857,5.489 79.857,5.489 89.857,8.321 9.857,13.489 89.857,18.378 9.857,23.489 89.857,28.489 9.857,33.489 19.857,33.489 24.857,33.489 89.857,38.494 64.857,48.407 54.857,48.489 69.857,48.489 77.644,48.489 84.857,48.489 89.857,48.489
DRIVEN_SHIELD_1: R220.1 U200.12 | length 5.9
  Bottom Layer w0.2: U200.12@31.25,53.305 31.771,53.305 33.1,51.976 33.1,50.177 33.622,49.655 R220.1@34.625,49.655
